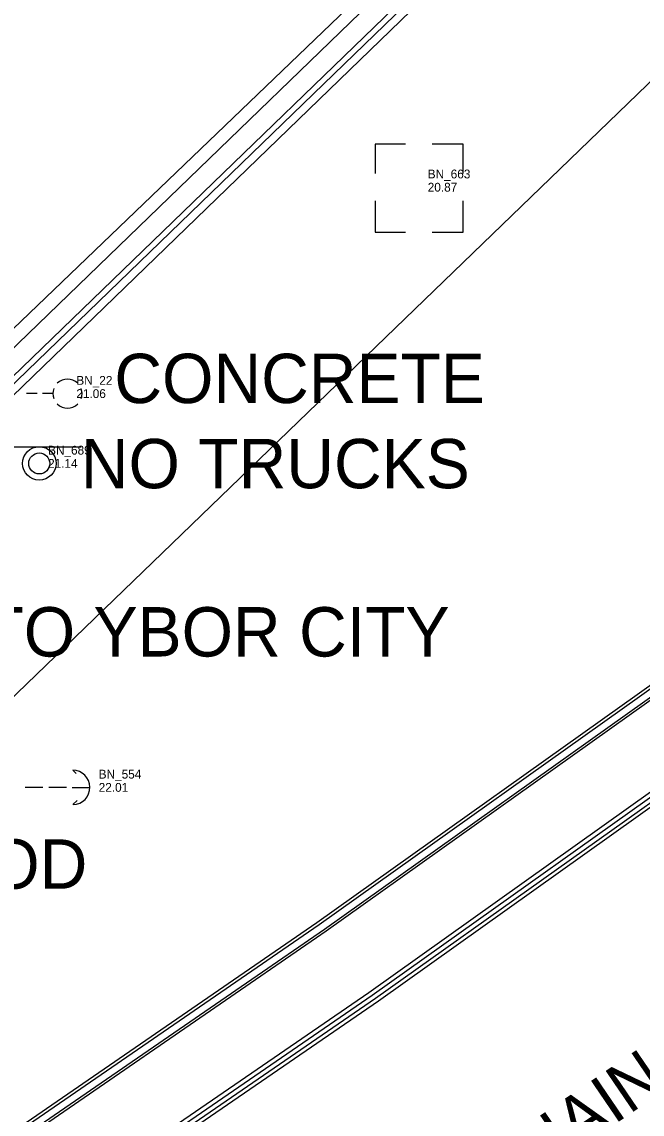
# Model space of a CAD drawing. Extents: x 509744 to 512285, y 1314862 to 1316822.
# Drawn here: x 510540.9 to 510576.1, y 1315940.7 to 1316002.7 of the extents above; entities that cross this region are included whole.
import ezdxf

# ---------------------------------------------------------------- set-up
doc = ezdxf.new("R2010")
doc.units = 0
for name, color, linetype in [('CGBack_ep', 7, 'Continuous'), ('CGep_ep', 7, 'Continuous'), ('CGFace_ep', 7, 'Continuous'), ('GuyWireAnchor_ep', 7, 'Continuous'), ('Luminaire_ep', 7, 'Continuous'), ('PavtAsphalt_ep', 7, 'Continuous'), ('PMRK_ep', 7, 'Continuous'), ('PullBox_ep', 7, 'Continuous'), ('RailroadTracks_ep', 7, 'Continuous'), ('RWLine_ep', 7, 'Continuous'), ('SignSingle_ep', 7, 'Continuous'), ('TextElevLabel', 7, 'Continuous'), ('TextPtLabel', 7, 'Continuous'), ('TextTopoLabel_ep', 7, 'Continuous'), ('TextUtilLabel_ep', 7, 'Continuous')]:
    doc.layers.add(name, color=color, linetype=linetype)

msp = doc.modelspace()

# ---------------------------------------------------------------- linework, layer by layer
at = {"layer": 'CGBack_ep'}
msp.add_lwpolyline([(510906.619, 1316389.372), (510906.094, 1316388.771), (510873.175, 1316351.137), (510840.313, 1316313.453), (510807.488, 1316275.737), (510774.647, 1316238.034), (510741.785, 1316200.35), (510708.978, 1316162.618), (510676.101, 1316124.947), (510643.265, 1316087.24), (510610.387, 1316049.569), (510574.578, 1316014.543), (510538.643, 1315979.773), (510535.201, 1315976.45), (510533.049, 1315974.36), (510531.944, 1315973.343)], dxfattribs=at)
at = {"layer": 'CGep_ep'}
msp.add_lwpolyline([(510741.133, 1316200.92), (510708.324, 1316163.19), (510675.447, 1316125.519), (510642.649, 1316087.779), (510609.794, 1316050.088), (510574.024, 1316015.104), (510538.089, 1315980.334), (510534.647, 1315977.011), (510532.5, 1315974.915), (510530.292, 1315972.882), (510528.11, 1315970.821), (510525.996, 1315968.692), (510524.588, 1315967.118), (510523.15, 1315965.736), (510520.573, 1315962.735), (510517.125, 1315957.899), (510513.652, 1315953.084), (510511.433, 1315949.796), (510511.381, 1315949.707)], dxfattribs=at)
at = {"layer": 'CGFace_ep'}
msp.add_lwpolyline([(510906.225, 1316389.717), (510905.7, 1316389.116), (510872.806, 1316351.459), (510839.944, 1316313.775), (510807.114, 1316276.063), (510774.274, 1316238.36), (510741.428, 1316200.662), (510708.597, 1316162.951), (510675.716, 1316125.283), (510642.909, 1316087.551), (510610.035, 1316049.877), (510574.249, 1316014.876), (510538.32, 1315980.1), (510534.878, 1315976.777), (510532.728, 1315974.684), (510531.649, 1315973.653)], dxfattribs=at)
at = {"layer": 'GuyWireAnchor_ep'}
for p, q in [((510543.819, 1315960.243), (510544.012, 1315960.05)), ((510541.125, 1315959.28), (510542.125, 1315959.28)), ((510542.459, 1315959.28), (510543.459, 1315959.28)), ((510543.792, 1315959.27), (510544.792, 1315959.27)), ((510543.834, 1315958.297), (510544.072, 1315958.53))]:
    msp.add_line(p, q, dxfattribs=at)
msp.add_arc((510543.819, 1315959.27), 0.973, 271.13997, 90.0059, dxfattribs=at)
at = {"layer": 'Luminaire_ep'}
for p, q in [((510541.799, 1315981.607), (510541.199, 1315981.607)), ((510542.699, 1315981.607), (510542.099, 1315981.607))]:
    msp.add_line(p, q, dxfattribs=at)
for start, end in [(45, 135), (159.91155, 200.08845), (339.91155, 20.08845), (225, 315)]:
    msp.add_arc((510543.524, 1315981.607), 0.825, start, end, dxfattribs=at)
at = {"layer": 'PavtAsphalt_ep'}
msp.add_lwpolyline([(510573.224, 1316015.914), (510537.289, 1315981.144), (510533.846, 1315977.821), (510531.697, 1315975.728), (510529.48, 1315973.704), (510527.307, 1315971.634), (510525.232, 1315969.466), (510523.749, 1315967.787), (510522.403, 1315966.332), (510519.791, 1315963.358), (510516.341, 1315958.525), (510512.867, 1315953.71), (510511.381, 1315949.707), (510510.662, 1315948.062), (510510.028, 1315946.347), (510509.316, 1315944.653), (510508.639, 1315942.949), (510508.051, 1315941.222), (510505.991, 1315934.237), (510505.673, 1315932.44), (510505.452, 1315930.617), (510504.719, 1315921.192), (510511.116, 1315924.575), (510510.582, 1315921.202)], dxfattribs=at)
at = {"layer": 'PMRK_ep'}
msp.add_lwpolyline([(510904.086, 1316390.528), (510871.21, 1316352.856), (510838.345, 1316315.173), (510805.495, 1316277.479), (510772.752, 1316239.691), (510739.91, 1316201.99), (510707.064, 1316164.292), (510674.247, 1316126.568), (510641.452, 1316088.825), (510608.591, 1316051.141), (510572.788, 1316016.355), (510536.711, 1315981.729), (510533.269, 1315978.406), (510531.042, 1315976.391), (510528.825, 1315974.367), (510526.652, 1315972.298), (510524.577, 1315970.129)], dxfattribs=at)
at = {"layer": 'PullBox_ep'}
for points in [[(510562.691, 1315995.765), (510560.958, 1315995.765), (510560.958, 1315994.09)], [(510565.953, 1315994.09), (510565.953, 1315995.765), (510564.191, 1315995.765)], [(510560.958, 1315992.538), (510560.958, 1315990.765)], [(510564.191, 1315990.765), (510565.953, 1315990.765), (510565.953, 1315992.538)], [(510560.958, 1315990.765), (510562.691, 1315990.765)]]:
    msp.add_lwpolyline(points, dxfattribs=at)
at = {"layer": 'RailroadTracks_ep'}
for points in [[(510799.573, 1316167.71), (510782.819, 1316149.146), (510765.786, 1316130.845), (510748.403, 1316112.876), (510730.712, 1316095.208), (510712.654, 1316077.904), (510694.36, 1316060.862), (510675.674, 1316044.251), (510656.696, 1316027.859), (510637.448, 1316011.896), (510617.968, 1315996.226), (510598.14, 1315980.994), (510578.041, 1315966.104), (510557.655, 1315951.588), (510537.042, 1315937.412), (510516.179, 1315923.572), (510511.116, 1315920.485)], [(510799.702, 1316167.596), (510782.948, 1316149.032), (510765.915, 1316130.732), (510748.532, 1316112.762), (510730.841, 1316095.094), (510712.783, 1316077.79), (510694.489, 1316060.748), (510675.804, 1316044.137), (510656.825, 1316027.745), (510637.577, 1316011.783), (510618.097, 1315996.112), (510598.269, 1315980.88), (510578.17, 1315965.99), (510557.784, 1315951.474), (510537.171, 1315937.298), (510516.308, 1315923.458), (510511.218, 1315920.355)], [(510800.008, 1316167.327), (510783.254, 1316148.763), (510766.221, 1316130.462), (510748.838, 1316112.492), (510731.147, 1316094.824), (510713.089, 1316077.521), (510694.795, 1316060.479), (510676.109, 1316043.868), (510657.131, 1316027.476), (510637.883, 1316011.513), (510618.403, 1315995.843), (510598.575, 1315980.611), (510578.476, 1315965.721), (510558.09, 1315951.205), (510537.477, 1315937.029), (510516.614, 1315923.188), (510511.444, 1315920.037)], [(510800.113, 1316167.234), (510783.359, 1316148.67), (510766.326, 1316130.369), (510748.943, 1316112.4), (510731.252, 1316094.732), (510713.194, 1316077.428), (510694.9, 1316060.386), (510676.215, 1316043.775), (510657.236, 1316027.383), (510637.988, 1316011.421), (510618.508, 1315995.75), (510598.68, 1315980.518), (510578.581, 1315965.628), (510558.195, 1315951.112), (510537.582, 1315936.936), (510516.719, 1315923.096), (510511.512, 1315919.921)], [(510803.199, 1316164.287), (510786.44, 1316145.727), (510769.407, 1316127.427), (510752.024, 1316109.457), (510734.055, 1316091.517), (510715.997, 1316074.214), (510697.703, 1316057.171), (510679.018, 1316040.561), (510659.793, 1316023.96), (510640.546, 1316007.997), (510621.011, 1315992.396), (510601.183, 1315977.164), (510581.114, 1315962.236), (510560.604, 1315947.624), (510539.991, 1315933.448), (510519.128, 1315919.608), (510511.238, 1315914.78)], [(510803.39, 1316164.118), (510786.631, 1316145.559), (510769.598, 1316127.258), (510752.215, 1316109.288), (510734.246, 1316091.349), (510716.188, 1316074.045), (510697.894, 1316057.003), (510679.209, 1316040.392), (510659.984, 1316023.791), (510640.737, 1316007.829), (510621.202, 1315992.227), (510601.374, 1315976.995), (510581.305, 1315962.067), (510560.795, 1315947.456), (510540.182, 1315933.28), (510519.319, 1315919.439), (510511.347, 1315914.562)], [(510803.583, 1316163.948), (510786.824, 1316145.389), (510769.791, 1316127.088), (510752.408, 1316109.119), (510734.439, 1316091.179), (510716.381, 1316073.875), (510698.087, 1316056.833), (510679.402, 1316040.222), (510660.177, 1316023.621), (510640.93, 1316007.659), (510621.395, 1315992.057), (510601.567, 1315976.825), (510581.498, 1315961.897), (510560.988, 1315947.286), (510540.375, 1315933.11), (510519.512, 1315919.269), (510511.446, 1315914.335)], [(510803.739, 1316163.811), (510786.98, 1316145.251), (510769.947, 1316126.951), (510752.564, 1316108.981), (510734.595, 1316091.041), (510716.537, 1316073.738), (510698.243, 1316056.696), (510679.558, 1316040.085), (510660.333, 1316023.484), (510641.086, 1316007.521), (510621.551, 1315991.92), (510601.723, 1315976.688), (510581.654, 1315961.76), (510561.144, 1315947.148), (510540.531, 1315932.972), (510519.668, 1315919.132), (510511.534, 1315914.155)]]:
    msp.add_lwpolyline(points, dxfattribs=at)
at = {"layer": 'RWLine_ep'}
msp.add_line((510616.27, 1316037.666), (510510.666, 1315935.625), dxfattribs=at)
at = {"layer": 'SignSingle_ep'}
msp.add_line((510539.547, 1315978.597), (510544.297, 1315978.597), dxfattribs=at)
for radius in [0.95, 0.594]:
    msp.add_circle((510541.922, 1315977.647), radius, dxfattribs=at)

# ---------------------------------------------------------------- texts
at = {"layer": 'TextElevLabel'}
for s, p in [('20.87', (510563.945, 1315993.065)), ('21.06', (510544.024, 1315981.357)), ('21.14', (510542.422, 1315977.397)), ('22.01', (510545.292, 1315959.02))]:
    msp.add_text(s, height=0.5, dxfattribs=at).set_placement(p)
at = {"layer": 'TextPtLabel'}
for s, p in [('BN_663', (510563.945, 1315993.815)), ('BN_22', (510544.024, 1315982.107)), ('BN_689', (510542.422, 1315978.147)), ('BN_554', (510545.292, 1315959.77))]:
    msp.add_text(s, height=0.5, dxfattribs=at).set_placement(p)
at = {"layer": 'TextTopoLabel_ep'}
for s, p in [('NO TRUCKS', (510544.279, 1315976.238)), ('TO YBOR CITY', (510538.759, 1315966.694)), ('WOOD', (510532.586, 1315953.522))]:
    msp.add_text(s, height=2.8, dxfattribs=at).set_placement(p)
msp.add_text('6 FT CHAIN LINK FENCE', height=2.8, rotation=34.22564, dxfattribs=at).set_placement((510560.733, 1315930.752))
at = {"layer": 'TextUtilLabel_ep'}
msp.add_text('CONCRETE', height=2.8, dxfattribs=at).set_placement((510546.179, 1315981.069))

doc.saveas('drawing.dxf')
